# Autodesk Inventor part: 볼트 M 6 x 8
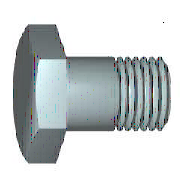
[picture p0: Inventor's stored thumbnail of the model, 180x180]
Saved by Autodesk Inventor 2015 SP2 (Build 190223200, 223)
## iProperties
Created: 2012-02
Part Number: 볼트 M 6 x 8
Material: 강철, 연강
Description: 6각 머리 볼트 및 6각 머리 나사
Document SubType Name: Modeling
Standard: KS B 1002
Designer: mduedu
Standards Organization: KS
Language: ko-KR
Size Designation: C  M 6 x 12
Categories: <MemberInstance><Categories><Category DisplayName="조임쇠" InternalName="e4da775c-781d-43d5-af7c-5136215cf5a6" Mnemonic="FSTN"><Category DisplayName="볼트" InternalN
Density: 1 g/cm^3
Appearance: 강철
IsCustomPart: 1
Author: mduedu
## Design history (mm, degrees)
sketch "스케치1"
  geometry: L1 (0, 3)-(8, 3); L2 (8, 3)-(8, 0); L3 (8, 0)-(0, 0); L4 (-2.4, 0)-(14.4, 0) reference; L5 (0, -0.6)-(0, 3.6) reference; L6 (0, 3)-(0, 0)
  constraints: 8 end point, 3 point on line, 1 collinear
  dimensions: "d2" = 6 diameter of L1 L3 (= GD); "d59" = 8 distance between parallel lines of L2 L5 (= NLG)
revolve "본체" sketch "스케치1" stored, may be unused: angle "d12" = 90 deg
sketch "스케치2"
  geometry: L1 (0, 5.774)-(5, 2.887); L2 (5, 2.887)-(5, -2.887); L3 (5, -2.887)-(0, -5.774); L4 (0, -5.774)-(-5, -2.887); L5 (-5, -2.887)-(-5, 2.887); L6 (-5, 2.887)-(0, 5.774); L7 (-7, 0)-(7, 0) reference; L8 (0, 8.083)-(0, -8.083) reference; 2 further points
  constraints: 12 end point, 2 midpoint, 1 coincident, 1 vertical, 11 other
  dimensions: "d11" = 10 distance between parallel lines of L5 L2 (= SW)
extrude "머리" join sketch "스케치2" distance "d3" = 4 (= KOH); taper "d4" = 0 deg
revolve "모따기1" stored, may be unused: angle "d21" = 90 deg
workplane "Work Plane1"
body "Solid1"
feature "스레드" dims "d15" = 9 (= GEL), "d16" = 0
chamfer "모따기2" distance "d6" = 0.61345 (= -0.5 x SPD + 0.5 x GD); stored, may be unused: second distance "d7" = 0.61355 (computed from GUL), angle "d55" = 45 deg
sketch "스케치4"
  geometry: L1 (-3.423, 6)-(-4, 5); L2 (-1.1, 0)-(-0.234, 0); L3 (-4.753, 0)-(0.519, 0) reference; L4 (-4, 6)-(-3.423, 6); L5 (-4, 5)-(-4, 6); L6 (0, 7.2)-(0, -1.2) reference
  constraints: 8 end point, 1 parallel, 1 perpendicular, 1 point on line
  dimensions: "d65" = 10 diameter of L1.end L2 (= SW); "d67" = 30 deg angle of L1 L5 (= ANG1); "d68" = 12 diameter of L4 L2 (= 1.2 x SW); "d69" = 4 distance between parallel lines of L5 L6 (= KOH)
other parameters: "NLG" = 8 [user parameter; used in 1 equation term], "GD" = 6 (= NND) [user parameter; used in 2 equation terms], "BDM" = 6 (= NND) [user parameter], "KOH" = 4 [user parameter; used in 2 equation terms], "GEL" = 9 [user parameter; used in 1 equation term], "SW" = 10 [user parameter; used in 5 equation terms], "SPD" = 4.7731 (= NND - 1.2269 x PTC) [user parameter; used in 1 equation term], "SD2" = 6 (= NND) [user parameter], "SD" = 0 [user parameter], "ANG1" = 30 deg [user parameter; used in 1 equation term], "GAL" = 0.61345 (= 0.61345 x PTC) [user parameter], "GUL" = 0.61345 (= 0.61345 x PTC) [user parameter; used in 1 equation term], "d8" = 0, "RR" = 0.25 [user parameter], "d58" = 0, "RR1" = 0.1 [user parameter], "GD1" = 4.7731 (= THREADDIA - 1.2269 x PTC) [user parameter], "THREADDIA" = 6 [user parameter; used in 1 equation term], "TOA" = 30 deg [user parameter], "PTC" = 1 [user parameter; used in 5 equation terms], "NND" = 6 [user parameter; used in 4 equation terms], "E0" = 11.55 (= 1.155 x SW) [user parameter]
